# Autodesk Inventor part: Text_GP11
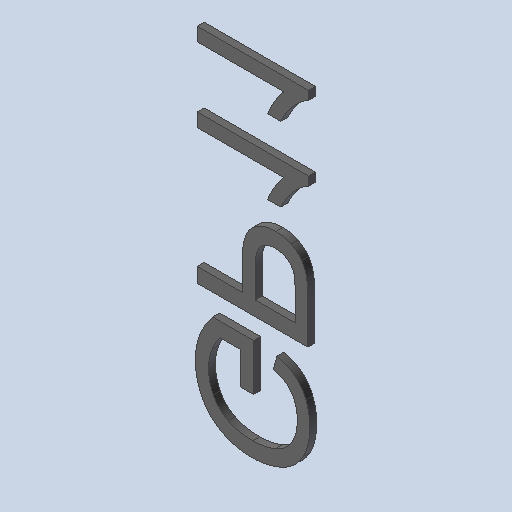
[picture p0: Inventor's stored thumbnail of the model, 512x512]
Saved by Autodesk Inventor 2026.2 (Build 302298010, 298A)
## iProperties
Created: 2026-10
Part Number: Text_GP11
Material: Générique
Document SubType Name: Modeling
Designer: mel
Density: 1 g/cm^3
Appearance: Par défaut
Author: mel
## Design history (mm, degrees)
feature "Base1"
feature "Base2"
feature "Base3"
feature "Base4"
node "Solide1"
node "Solide2"
node "Solide3"
node "Solide4"
